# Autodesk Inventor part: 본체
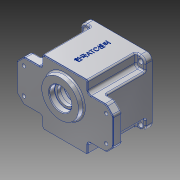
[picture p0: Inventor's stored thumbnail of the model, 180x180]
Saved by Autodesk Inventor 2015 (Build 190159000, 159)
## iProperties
Created: 2016-02
Part Number: 본체
Material: Aluminum 6061
Document SubType Name: Modeling
Designer: Administrator
Density: 2.7 g/cm^3
Appearance: Aluminum - Flat
Mass: 873.99 g
Surface Area: 760.368 cm^2
Volume: 323.7 cm^3
Author: Administrator
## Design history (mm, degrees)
sketch "Sketch1"
  geometry: L1 (33, 30)-(33, 47); L2 (33, 47)-(-33, 47); L3 (-33, 47)-(-33, 30); L4 (-33, 30)-(-70, 30); L5 (-70, 30)-(-70, -30); L6 (-70, -30)-(-33, -30); L7 (-33, -30)-(-33, -47); L8 (-33, -47)-(33, -47); L9 (33, -47)-(33, -30); L10 (33, -30)-(70, -30); L11 (70, -30)-(70, 30); L12 (70, 30)-(33, 30); 2 further points
  constraints: 24 end point, 10 perpendicular, 2 vertical alignment, 1 horizontal, 1 horizontal alignment, 1 midpoint, 1 point on line, 1 vertical
  dimensions: "d11" = 140 distance between parallel lines of L5 L11; "d12" = 70 distance from line of L11 point (0, 0); "d13" = 66 distance of L1.end L2.end; "d14" = 66 distance of L7.end L8.end; "d15" = 94 distance between parallel lines of L8 L2; "d16" = 47 distance from line of L2 point (0, 0); "d17" = 60 distance between parallel lines of L6 L4; "d18" = 30 distance from line of point (0, 0) L4
extrude "Extrusion1" new body sketch "Sketch1" distance "d19" = 13; taper "d20" = 0 deg
chamfer "Chamfer1" distance "d21" = 10; stored, may be unused: second distance "d22" = 2, angle "d23" = 45 deg
sketch "Sketch2"
  geometry: L1 (47, -47)-(-47, -47); L2 (-47, -47)-(-47, 47); L3 (-47, 47)-(47, 47); L4 (47, 47)-(47, -47); L5 (47, -47)-(-47, 47); L6 (-47, -47)-(47, 47); 1 further point
  constraints: 12 end point, 2 midpoint, 2 parallel, 1 horizontal, 1 perpendicular
  dimensions: "d24" = 94 distance of L2.end L3.end; "d25" = 94 distance of L1.end L2.end
extrude "Extrusion2" join sketch "Sketch2" distance "d26" = 67; taper "d27" = 0 deg
sketch "Sketch3"
  geometry: L1 (-47, 30)-(-33, 30) reference; L2 (-33, 30)-(-33, 47) reference; L3 (-33, 47)-(-47, 47) reference; L4 (-47, 47)-(-47, 30) reference; L5 (-33, -47)-(-33, -30) reference; L6 (-33, -30)-(-47, -30) reference; L7 (-47, -30)-(-47, -47) reference; L8 (-47, -47)-(-33, -47) reference; L9 (33, -30)-(33, -47) reference; L10 (33, -47)-(47, -47) reference; L11 (47, -47)-(47, -30) reference; L12 (47, -30)-(33, -30) reference; L13 (33, 30)-(47, 30) reference; L14 (47, 30)-(47, 47) reference; L15 (47, 47)-(33, 47) reference; L16 (33, 47)-(33, 30) reference; 1 further point
extrude "Extrusion3" cut sketch "Sketch3" distance "d28" = 57; taper "d29" = 0 deg
fillet "Fillet1" dims "d30" = 8
sketch "Sketch4"
  geometry: L1 (-47, 30)-(-47, 39) reference; L2 (-33, 30)-(-47, 30) reference; L3 (-33, 47)-(-33, 30) reference; L4 (-39, 47)-(-33, 47) reference; L5 (-33, -47)-(-39, -47) reference; L6 (-33, -30)-(-33, -47) reference; L7 (-47, -30)-(-33, -30) reference; L8 (-47, -39)-(-47, -30) reference; L9 (47, -30)-(47, -39) reference; L10 (33, -30)-(47, -30) reference; L11 (33, -47)-(33, -30) reference; L12 (39, -47)-(33, -47) reference; L13 (33, 47)-(39, 47) reference; L14 (33, 30)-(33, 47) reference; L15 (47, 30)-(33, 30) reference; L16 (47, 39)-(47, 30) reference; C1 r 3.5 at (-40, 40); C2 r 3.5 at (-40, -40); C3 r 3.5 at (40, 40); C4 r 3.5 at (40, -40); A1 r 8 centre (-39, 39) between (-39, 47) and (-47, 39) reference; A2 r 8 centre (-39, -39) between (-47, -39) and (-39, -47) reference; A3 r 8 centre (39, -39) between (39, -47) and (47, -39) reference; A4 r 8 centre (39, 39) between (47, 39) and (39, 47) reference; 1 further point
  constraints: 4 centre point
  dimensions: "d130" = 7 diameter of C1; "d131" = 7 diameter of C2; "d132" = 7 diameter of C3; "d133" = 7 diameter of C4; "d134" = 80 distance of C4.centre C3.centre; "d135" = 40 horizontal distance of point (0, 0) C3.centre; "d136" = 40 horizontal distance of C3.centre point (0, 0); "d137" = 40 horizontal distance of C4.centre point (0, 0); "d138" = 80 distance of C3.centre C1.centre; "d139" = 80 distance of C2.centre C1.centre; "d140" = 40 horizontal distance of point (0, 0) C1.centre; "d141" = 40 horizontal distance of point (0, 0) C2.centre
  node "Projected Loop5"
  node "Projected Loop6"
  node "Projected Loop7"
  node "Projected Loop8"
sketch "Sketch5"
  geometry: C1 r 28 at (0, 11); 1 further point
  constraints: 1 centre point, 1 vertical alignment
  dimensions: "d37" = 56 diameter of C1; "d38" = 11 distance of point (0, 0) C1.centre
extrude "Extrusion5" join sketch "Sketch5" distance "d39" = 7; taper "d40" = -10 deg
sketch "Sketch6"
  geometry: C1 r 26.766 at (0, 0) reference; C2 r 16 at (0, 0); 1 further point
  constraints: 1 centre point, 1 coincident
  dimensions: "d41" = 32 diameter of C2
extrude "Extrusion6" cut sketch "Sketch6" distance "d42" = 8; taper "d43" = 0 deg
hole "Hole1" diameter "d46" = 25; stored, may be unused: countersink angle "d50" = 90 deg, drill point angle "d52" = 0 deg; dims "d44" = 10, "d45" = 10, "d47" = 6, "d48" = 25, "d49" = 5, "d51" = 5
sketch "Sketch7"
  geometry: C1 r 43 at (0, 0); 1 further point
  constraints: 1 centre point, 1 coincident
  dimensions: "d53" = 86 diameter of C1
extrude "Extrusion7" cut sketch "Sketch7" distance "d54" = 9; taper "d55" = 0 deg
sketch "Sketch8"
  geometry: C1 r 40 at (0, 0); 1 further point
  constraints: 1 centre point, 1 coincident
  dimensions: "d56" = 80 diameter of C1
extrude "Extrusion8" cut sketch "Sketch8" distance "d57" = 62; taper "d58" = 0 deg
sketch "Sketch10"
  geometry: A1 r 40 centre (0, 0) between (39.148, 8.214) and (39.148, -8.214) reference; A2 r 36 centre (0, 0) between (36, 0) and (35.778, 3.995); A3 r 4 centre (36, 0) between (35.852, 3.997) and (35.852, -3.997); A4 r 3.5 centre (35.722, -7.495) between (39.148, -8.214) and (35.778, -3.995); A5 r 3.5 centre (35.722, 7.495) between (35.778, 3.995) and (39.148, 8.214); 1 further point
  constraints: 13 point on circle, 4 centre point, 4 tangent, 1 coincident, 1 horizontal alignment
  dimensions: "d63" = 36 radius of A2; "d64" = 4 radius of A3; "d65" = 3.5 radius of A4; "d66" = 3.5 radius of A5
extrude "Extrusion9" join sketch "Sketch10" stored distance "d67" = 62; taper "d68" = 0 deg
mirror "Mirror1"
sketch "Sketch11"
  geometry: C1 r 21 at (0, -11); C2 r 15 at (0, 20); 1 further point
  constraints: 2 centre point, 2 vertical alignment
  dimensions: "d69" = 21 radius of C1; "d70" = 15 radius of C2; "d71" = 11 distance of point (0, 0) C1.centre; "d72" = 20 distance of C2.centre point (0, 0)
extrude "Extrusion10" join sketch "Sketch11" distance "d73" = 7; taper "d74" = 0 deg
sketch "Sketch12"
  geometry: A1 r 4 centre (36, 0) between (35.852, 3.997) and (35.852, -3.997) reference; A2 r 4 centre (-36, 0) between (-35.852, -3.997) and (-35.852, 3.997) reference; 1 further point
hole "Hole2" sketch "Sketch12" at (36, 0), (-36, 0) diameter "d75" = 3.242; stored, may be unused: countersink angle "d79" = 82 deg, drill point angle "d81" = 118 deg; dims "d76" = 7, "d77" = 3.023, "d78" = 5, "d80" = 9
sketch "Sketch13"
  geometry: C1 r 17.5 at (0, -11); A1 r 21 centre (0, -11) between (-8.978, 7.984) and (8.978, 7.984) reference; 1 further point
  constraints: 1 centre point, 1 coincident
  dimensions: "d83" = 35 diameter of C1
extrude "Extrusion11" cut sketch "Sketch13" distance "d84" = 10; taper "d85" = 0 deg
sketch "Sketch14"
  geometry: C1 r 11 at (0, 20); A1 r 15 centre (0, 20) between (8.978, 7.984) and (-8.978, 7.984) reference; 1 further point
  constraints: 1 centre point, 1 coincident
  dimensions: "d87" = 22 diameter of C1
extrude "Extrusion12" cut sketch "Sketch14" distance "d88" = 7; taper "d89" = 0 deg
sketch "Sketch15"
  geometry: C1 r 26.766 at (0, -31) reference; C2 r 11 at (0, 0) reference; C3 r 9.5 at (0, 0); 1 further point
  constraints: 1 centre point, 1 coincident
  dimensions: "d91" = 19 diameter of C3
extrude "Extrusion13" cut sketch "Sketch15" distance "d92" = 1; taper "d93" = 0 deg
sketch "Sketch16"
  geometry: C1 r 12.5 at (0, 11) reference; 5 further points
  constraints: 2 horizontal alignment, 2 vertical alignment
  dimensions: "d94" = 38 distance of point (60, -19) point (60, 19); "d95" = 60 horizontal distance of point (60, 19) C1.centre; "d97" = 19 vertical distance of point (60, 19) point (0, 0); "d98" = 60 horizontal distance of C1.centre point (-60, 19)
hole "Hole3" sketch "Sketch16" at (-60, 19), (-60, -19), (60, 19), (60, -19) diameter "d99" = 5; stored, may be unused: countersink angle "d103" = 82 deg, drill point angle "d105" = 0 deg; dims "d100" = 7, "d101" = 22, "d102" = 7, "d104" = 9
sketch "Sketch17"
  geometry: C1 r 2.5 at (60, -19) reference; C2 r 2.5 at (60, 19) reference; C3 r 2.5 at (-60, 19) reference; C4 r 2.5 at (-60, -19) reference; C5 r 4.5 at (60, -19); C6 r 4.5 at (60, 19); C7 r 4.5 at (-60, -19); C8 r 4.5 at (-60, 19); 1 further point
  constraints: 4 centre point, 4 coincident
  dimensions: "d106" = 9 diameter of C5; "d107" = 9 diameter of C6; "d108" = 9 diameter of C7; "d109" = 9 diameter of C8
extrude "Extrusion14" cut sketch "Sketch17" distance "d110" = 4; taper "d111" = 0 deg
fillet "Fillet2" dims "d112" = 2
sketch "Sketch18"
  geometry: L1 (-33, 30)-(-33, 47) reference; L2 (-60, 30)-(-33, 30) reference; L3 (-70, 20)-(-60, 30) reference; L4 (-70, -20)-(-70, 20) reference; L5 (-60, -30)-(-70, -20) reference; L6 (-33, -30)-(-60, -30) reference; L7 (-33, -47)-(-33, -30) reference; L8 (33, -47)-(-33, -47) reference; L9 (33, -30)-(33, -47) reference; L10 (60, -30)-(33, -30) reference; L11 (70, -20)-(60, -30) reference; L12 (70, 20)-(70, -20) reference; L13 (60, 30)-(70, 20) reference; L14 (33, 30)-(60, 30) reference; L15 (33, 47)-(33, 30) reference; L16 (-33, 47)-(33, 47) reference; L17 (32, 46)-(32, 34); L18 (37, 29)-(57.515, 29); L19 (61.05, 27.536)-(69, 19.586); L20 (69, 19.586)-(69, -17.515); L21 (67.536, -21.05)-(61.05, -27.536); L22 (57.515, -29)-(37, -29); L23 (32, -34)-(32, -46); L24 (32, -46)-(-32, -46); L25 (-32, -46)-(-32, -34); L26 (-37, -29)-(-59.586, -29); L27 (-59.586, -29)-(-69, -19.586); L28 (-69, -19.586)-(-69, 19.586); L29 (-69, 19.586)-(-59.586, 29); L30 (-59.586, 29)-(-37, 29); L31 (-32, 34)-(-32, 46); L32 (-32, 46)-(32, 46); C1 r 28 at (0, 11) reference; C2 r 2.5 at (60, -19) reference; C3 r 2.5 at (-60, -19) reference; C4 r 2.5 at (-60, 19) reference; C5 r 2.5 at (60, 19) reference; A1 r 5 centre (-37, 34) between (-37, 29) and (-32, 34); A2 r 5 centre (-37, -34) between (-32, -34) and (-37, -29); A3 r 5 centre (37, -34) between (37, -29) and (32, -34); A4 r 5 centre (37, 34) between (32, 34) and (37, 29); A5 r 5 centre (57.515, 24) between (61.05, 27.536) and (57.515, 29); A6 r 5 centre (64, -17.515) between (67.536, -21.05) and (69, -17.515); A7 r 5 centre (57.515, -24) between (57.515, -29) and (61.05, -27.536); 8 further points
  constraints: 32 end point, 14 point on circle, 14 point on line, 14 tangent, 7 centre point, 5 equal radius, 15 other
  dimensions: "d148" = 1 distance between parallel lines of L16 L32; "d153" = 5 radius of A1; "d154" = 5 radius of A5
  node "Projected Loop14"
fillet "Fillet3" dims "d116" = 2
fillet "Fillet4" dims "d117" = 3
fillet "Fillet5" dims "d118" = 2
fillet "Fillet6" dims "d119" = 0.3
sketch "Sketch19"
  geometry: L1 (0, 0)-(78, 0) reference; 2 further points
  constraints: 1 vertical alignment, 1 other
  dimensions: "d120" = 40 distance from line of L1 point (39, -40)
emboss "Emboss1" sketch "Sketch19" dims "d121" = 0.5, "d122" = 0
fillet "Fillet7" dims "d123" = 5
fillet "Fillet8" dims "d124" = 5
fillet "Fillet10" dims "d126" = 2
chamfer "Chamfer2" distance "d127" = 1; stored, may be unused: second distance "d128" = 2, angle "d129" = 45 deg
extrude "Extrusion16" cut sketch "Sketch4" stored distance "d142" = 1; taper "d143" = 0 deg
fillet "Fillet11" dims "d144" = 2
extrude "Extrusion17" cut sketch "Sketch18" distance "d149" = 1; taper "d150" = 0 deg
fillet "Fillet12" dims "d151" = 5
fillet "Fillet13" dims "d152" = 5
fillet "Fillet14" dims "d155" = 2
chamfer "Chamfer3" distance "d157" = 1; stored, may be unused: second distance "d158" = 2, angle "d159" = 45 deg
body "Solid1"
node "Projected Loop1"
node "Projected Loop2"
node "Projected Loop3"
node "Projected Loop4"
workplane "Work Plane1"
node "Projected Loop10"
node "Projected Loop11"
node "Projected Loop12"
node "Projected Loop13"
